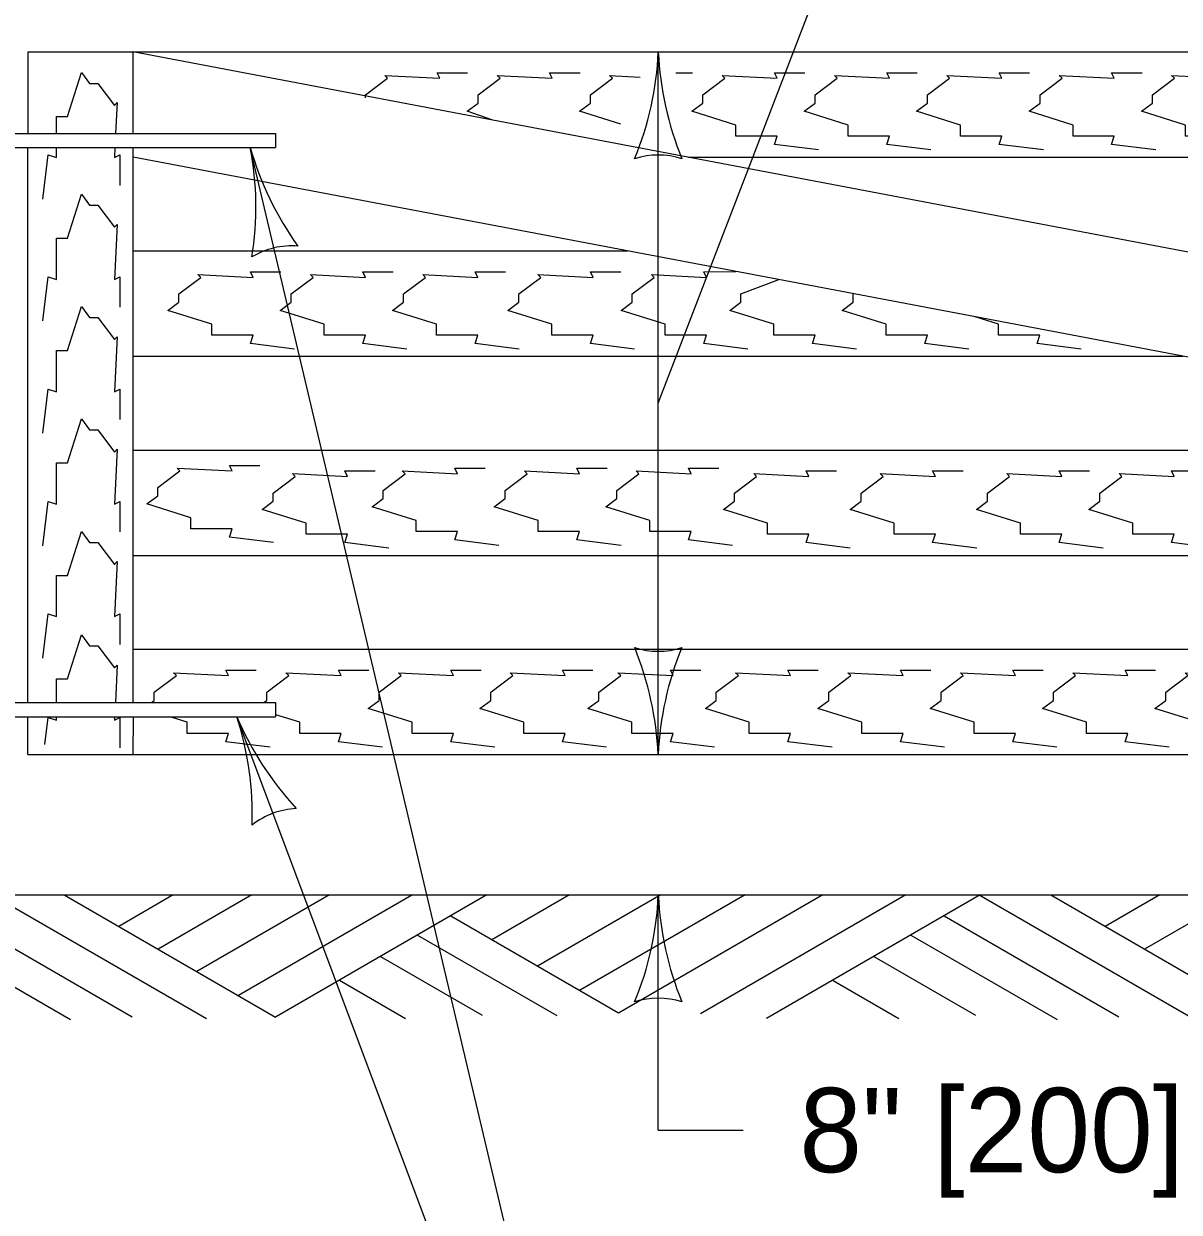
# Model space of a CAD drawing. Extents: x 49991.4 to 50021, y 49987.6 to 50011.4.
# Drawn here: x 50003.336 to 50004.158, y 50009.357 to 50010.203 of the extents above; entities that cross this region are included whole.
import ezdxf

# ---------------------------------------------------------------- set-up
doc = ezdxf.new("R2010")
doc.units = 0
for name, color, linetype in [('Level 1', 7, 'Continuous'), ('Level 2', 7, 'Continuous'), ('Level 3', 7, 'Continuous')]:
    doc.layers.add(name, color=color, linetype=linetype)

msp = doc.modelspace()

# ---------------------------------------------------------------- linework, layer by layer
at = {"layer": 'Level 1'}
for p, q in [((50003.3389, 50010.1834), (50005.6927, 50010.1834)), ((50003.3389, 50010.1834), (50003.3389, 50010.1253)), ((50005.6552, 50009.7582), (50003.4138, 50010.1834)), ((50003.4138, 50010.1834), (50003.4138, 50010.1253)), ((50003.3152, 50010.1253), (50003.5152, 50010.1253)), ((50003.5152, 50010.1253), (50003.5152, 50010.1153)), ((50003.2927, 50010.1153), (50003.5152, 50010.1153)), ((50003.3389, 50009.7202), (50003.3389, 50010.1153)), ((50003.4139, 50009.7202), (50003.4139, 50010.1153)), ((50005.6552, 50009.6833), (50003.4139, 50010.1085)), ((50003.80916, 50010.1084), (50005.6552, 50010.1084)), ((50003.4139, 50010.0417), (50003.76601, 50010.0417)), ((50003.4139, 50009.9667), (50004.16135, 50009.9667)), ((50003.4139, 50009.9), (50004.51294, 50009.9)), ((50003.4139, 50009.825), (50004.90828, 50009.825)), ((50003.4139, 50009.7582), (50005.26039, 50009.7582)), ((50003.3152, 50009.7202), (50003.5152, 50009.7202)), ((50003.5152, 50009.7202), (50003.5152, 50009.7102)), ((50003.2927, 50009.7102), (50003.5152, 50009.7102)), ((50003.3389, 50009.6833), (50003.3389, 50009.7102)), ((50003.41388, 50009.7102), (50003.41381, 50009.6833)), ((50003.3389, 50009.6833), (50005.7302, 50009.6833)), ((50001.4073, 50009.5833), (50004.5539, 50009.5833)), ((50003.3139, 50009.5833), (50003.4661, 50009.4954)), ((50003.3649, 50009.5833), (50003.51535, 50009.49641)), ((50003.44245, 50009.5833), (50003.40365, 50009.56092)), ((50003.49846, 50009.5833), (50003.43164, 50009.54475)), ((50003.55374, 50009.5833), (50003.45929, 50009.52879)), ((50003.6128, 50009.5833), (50003.4889, 50009.5117)), ((50003.6658, 50009.5833), (50003.51535, 50009.49641)), ((50003.7245, 50009.5833), (50003.66935, 50009.55147)), ((50003.7896, 50009.5833), (50003.70186, 50009.53263)), ((50003.84956, 50009.5833), (50003.7317, 50009.5153)), ((50003.90484, 50009.5833), (50003.7593, 50009.4993)), ((50003.9639, 50009.5833), (50003.8177, 50009.4988)), ((50004.0169, 50009.5833), (50003.8647, 50009.4954)), ((50004.0161, 50009.5833), (50004.1683, 50009.4954)), ((50004.0671, 50009.5833), (50004.21755, 50009.49641)), ((50004.14465, 50009.5833), (50004.10585, 50009.56092)), ((50004.20066, 50009.5833), (50004.13384, 50009.54475)), ((50003.28896, 50009.56843), (50003.4133, 50009.4966)), ((50003.64006, 50009.56843), (50003.75935, 50009.49933)), ((50003.99116, 50009.56843), (50004.1155, 50009.4966)), ((50003.2653, 50009.55477), (50003.3693, 50009.4947)), ((50003.6164, 50009.55477), (50003.7155, 50009.4976)), ((50003.9675, 50009.55477), (50004.0715, 50009.4947)), ((50003.59006, 50009.53956), (50003.6623, 50009.4978)), ((50003.94116, 50009.53956), (50004.0134, 50009.4978)), ((50003.56081, 50009.52267), (50003.6079, 50009.4954)), ((50003.9122, 50009.5225), (50003.959, 50009.4954))]:
    msp.add_line(p, q, dxfattribs=at)
for points in [[(50003.3594, 50010.1253), (50003.3594, 50010.1375), (50003.3673, 50010.1375), (50003.3771, 50010.1688), (50003.3829, 50010.161), (50003.3888, 50010.161), (50003.4006, 50010.1453), (50003.4026, 50010.1473), (50003.40143, 50010.1253)], [(50003.5794, 50010.1508), (50003.5794, 50010.1528), (50003.5951, 50010.1646), (50003.5931, 50010.1666), (50003.6323, 50010.1646), (50003.6304, 50010.1685), (50003.652, 50010.1685)], [(50003.66915, 50010.13496), (50003.6516, 50010.1411), (50003.6594, 50010.1469), (50003.6594, 50010.1528), (50003.6751, 50010.1646), (50003.6731, 50010.1666), (50003.7123, 50010.1646), (50003.7104, 50010.1685), (50003.732, 50010.1685)], [(50003.7611, 50010.1319), (50003.7316, 50010.1411), (50003.7394, 50010.1469), (50003.7394, 50010.1528), (50003.7551, 50010.1646), (50003.7531, 50010.1666), (50003.7747, 50010.1655)], [(50003.8002, 50010.1685), (50003.812, 50010.1685)], [(50003.9018, 50010.1136), (50003.8704, 50010.1175), (50003.8723, 50010.1234), (50003.8429, 50010.1234), (50003.8429, 50010.1313), (50003.8116, 50010.1411), (50003.8194, 50010.1469), (50003.8194, 50010.1528), (50003.8351, 50010.1646), (50003.8331, 50010.1666), (50003.8723, 50010.1646), (50003.8704, 50010.1685), (50003.892, 50010.1685)], [(50003.9818, 50010.1136), (50003.9504, 50010.1175), (50003.9523, 50010.1234), (50003.9229, 50010.1234), (50003.9229, 50010.1313), (50003.8916, 50010.1411), (50003.8994, 50010.1469), (50003.8994, 50010.1528), (50003.9151, 50010.1646), (50003.9131, 50010.1666), (50003.9523, 50010.1646), (50003.9504, 50010.1685), (50003.972, 50010.1685)], [(50004.0618, 50010.1136), (50004.0304, 50010.1175), (50004.0323, 50010.1234), (50004.0029, 50010.1234), (50004.0029, 50010.1313), (50003.9716, 50010.1411), (50003.9794, 50010.1469), (50003.9794, 50010.1528), (50003.9951, 50010.1646), (50003.9931, 50010.1666), (50004.0323, 50010.1646), (50004.0304, 50010.1685), (50004.052, 50010.1685)], [(50004.1418, 50010.1136), (50004.1104, 50010.1175), (50004.1123, 50010.1234), (50004.0829, 50010.1234), (50004.0829, 50010.1313), (50004.0516, 50010.1411), (50004.0594, 50010.1469), (50004.0594, 50010.1528), (50004.0751, 50010.1646), (50004.0731, 50010.1666), (50004.1123, 50010.1646), (50004.1104, 50010.1685), (50004.132, 50010.1685)], [(50004.2218, 50010.1136), (50004.1904, 50010.1175), (50004.1923, 50010.1234), (50004.1629, 50010.1234), (50004.1629, 50010.1313), (50004.1316, 50010.1411), (50004.1394, 50010.1469), (50004.1394, 50010.1528), (50004.1551, 50010.1646), (50004.1531, 50010.1666), (50004.1923, 50010.1646), (50004.1904, 50010.1685), (50004.212, 50010.1685)], [(50003.3496, 50010.0786), (50003.3535, 50010.11), (50003.3594, 50010.1081), (50003.3594, 50010.1153)], [(50003.40094, 50010.1153), (50003.4006, 50010.1081), (50003.4045, 50010.11), (50003.4045, 50010.0884)], [(50003.3496, 50009.9919), (50003.3535, 50010.0233), (50003.3594, 50010.0214), (50003.3594, 50010.0508), (50003.3673, 50010.0508), (50003.3771, 50010.0821), (50003.3829, 50010.0743), (50003.3888, 50010.0743), (50003.4006, 50010.0586), (50003.4026, 50010.0606), (50003.4006, 50010.0214), (50003.4045, 50010.0233), (50003.4045, 50010.0017)], [(50003.5288, 50009.9719), (50003.4974, 50009.9758), (50003.4993, 50009.9817), (50003.4699, 50009.9817), (50003.4699, 50009.9896), (50003.4386, 50009.9994), (50003.4464, 50010.0052), (50003.4464, 50010.0111), (50003.4621, 50010.0229), (50003.4601, 50010.0249), (50003.4993, 50010.0229), (50003.4974, 50010.0268), (50003.519, 50010.0268)], [(50003.6088, 50009.9719), (50003.5774, 50009.9758), (50003.5793, 50009.9817), (50003.5499, 50009.9817), (50003.5499, 50009.9896), (50003.5186, 50009.9994), (50003.5264, 50010.0052), (50003.5264, 50010.0111), (50003.5421, 50010.0229), (50003.5401, 50010.0249), (50003.5793, 50010.0229), (50003.5774, 50010.0268), (50003.599, 50010.0268)], [(50003.6888, 50009.9719), (50003.6574, 50009.9758), (50003.6593, 50009.9817), (50003.6299, 50009.9817), (50003.6299, 50009.9896), (50003.5986, 50009.9994), (50003.6064, 50010.0052), (50003.6064, 50010.0111), (50003.6221, 50010.0229), (50003.6201, 50010.0249), (50003.6593, 50010.0229), (50003.6574, 50010.0268), (50003.679, 50010.0268)], [(50003.7708, 50009.9719), (50003.7394, 50009.9758), (50003.7413, 50009.9817), (50003.7119, 50009.9817), (50003.7119, 50009.9896), (50003.6806, 50009.9994), (50003.6884, 50010.0052), (50003.6884, 50010.0111), (50003.7041, 50010.0229), (50003.7021, 50010.0249), (50003.7413, 50010.0229), (50003.7394, 50010.0268), (50003.761, 50010.0268)], [(50003.8515, 50009.9719), (50003.8201, 50009.9758), (50003.822, 50009.9817), (50003.7926, 50009.9817), (50003.7926, 50009.9896), (50003.7613, 50009.9994), (50003.7691, 50010.0052), (50003.7691, 50010.0111), (50003.7848, 50010.0229), (50003.7828, 50010.0249), (50003.822, 50010.0229), (50003.8201, 50010.0268), (50003.84299, 50010.0271)], [(50003.9288, 50009.9719), (50003.8974, 50009.9758), (50003.8993, 50009.9817), (50003.8699, 50009.9817), (50003.8699, 50009.9896), (50003.8386, 50009.9994), (50003.8464, 50010.0052), (50003.8464, 50010.0111), (50003.87343, 50010.02132)], [(50004.0088, 50009.9719), (50003.9774, 50009.9758), (50003.9793, 50009.9817), (50003.9499, 50009.9817), (50003.9499, 50009.9896), (50003.9186, 50009.9994), (50003.9264, 50010.0052), (50003.9264, 50010.01127)], [(50003.3496, 50009.9119), (50003.3535, 50009.9433), (50003.3594, 50009.9414), (50003.3594, 50009.9708), (50003.3673, 50009.9708), (50003.3771, 50010.0021), (50003.3829, 50009.9943), (50003.3888, 50009.9943), (50003.4006, 50009.9786), (50003.4026, 50009.9806), (50003.4006, 50009.9414), (50003.4045, 50009.9433), (50003.4045, 50009.9217)], [(50004.0888, 50009.9719), (50004.0574, 50009.9758), (50004.0593, 50009.9817), (50004.0299, 50009.9817), (50004.0299, 50009.9896), (50004.01333, 50009.99478)], [(50003.3496, 50009.8319), (50003.3535, 50009.8633), (50003.3594, 50009.8614), (50003.3594, 50009.8908), (50003.3673, 50009.8908), (50003.3771, 50009.9221), (50003.3829, 50009.9143), (50003.3888, 50009.9143), (50003.4006, 50009.8986), (50003.4026, 50009.9006), (50003.4006, 50009.8614), (50003.4045, 50009.8633), (50003.4045, 50009.8417)], [(50003.5139, 50009.8341), (50003.4825, 50009.838), (50003.4844, 50009.8439), (50003.455, 50009.8439), (50003.455, 50009.8518), (50003.4237, 50009.8616), (50003.4315, 50009.8674), (50003.4315, 50009.8733), (50003.4472, 50009.8851), (50003.4452, 50009.8871), (50003.4844, 50009.8851), (50003.4825, 50009.889), (50003.5041, 50009.889)], [(50003.596, 50009.8302), (50003.5646, 50009.8341), (50003.5665, 50009.84), (50003.5371, 50009.84), (50003.5371, 50009.8479), (50003.5058, 50009.8577), (50003.5136, 50009.8635), (50003.5136, 50009.8694), (50003.5293, 50009.8812), (50003.5273, 50009.8832), (50003.5665, 50009.8812), (50003.5646, 50009.8851), (50003.5862, 50009.8851)], [(50003.6742, 50009.8321), (50003.6428, 50009.836), (50003.6447, 50009.8419), (50003.6153, 50009.8419), (50003.6153, 50009.8498), (50003.584, 50009.8596), (50003.5918, 50009.8654), (50003.5918, 50009.8713), (50003.6075, 50009.8831), (50003.6055, 50009.8851), (50003.6447, 50009.8831), (50003.6428, 50009.887), (50003.6644, 50009.887)], [(50003.7612, 50009.8321), (50003.7298, 50009.836), (50003.7317, 50009.8419), (50003.7023, 50009.8419), (50003.7023, 50009.8498), (50003.671, 50009.8596), (50003.6788, 50009.8654), (50003.6788, 50009.8713), (50003.6945, 50009.8831), (50003.6925, 50009.8851), (50003.7317, 50009.8831), (50003.7298, 50009.887), (50003.7514, 50009.887)], [(50003.8406, 50009.8321), (50003.8092, 50009.836), (50003.8111, 50009.8419), (50003.7817, 50009.8419), (50003.7817, 50009.8498), (50003.7504, 50009.8596), (50003.7582, 50009.8654), (50003.7582, 50009.8713), (50003.7739, 50009.8831), (50003.7719, 50009.8851), (50003.8111, 50009.8831), (50003.8092, 50009.887), (50003.8308, 50009.887)], [(50003.9244, 50009.8302), (50003.893, 50009.8341), (50003.8949, 50009.84), (50003.8655, 50009.84), (50003.8655, 50009.8479), (50003.8342, 50009.8577), (50003.842, 50009.8635), (50003.842, 50009.8694), (50003.8577, 50009.8812), (50003.8557, 50009.8832), (50003.8949, 50009.8812), (50003.893, 50009.8851), (50003.9146, 50009.8851)], [(50004.0144, 50009.8302), (50003.983, 50009.8341), (50003.9849, 50009.84), (50003.9555, 50009.84), (50003.9555, 50009.8479), (50003.9242, 50009.8577), (50003.932, 50009.8635), (50003.932, 50009.8694), (50003.9477, 50009.8812), (50003.9457, 50009.8832), (50003.9849, 50009.8812), (50003.983, 50009.8851), (50004.0046, 50009.8851)], [(50004.1044, 50009.8302), (50004.073, 50009.8341), (50004.0749, 50009.84), (50004.0455, 50009.84), (50004.0455, 50009.8479), (50004.0142, 50009.8577), (50004.022, 50009.8635), (50004.022, 50009.8694), (50004.0377, 50009.8812), (50004.0357, 50009.8832), (50004.0749, 50009.8812), (50004.073, 50009.8851), (50004.0946, 50009.8851)], [(50004.1844, 50009.8302), (50004.153, 50009.8341), (50004.1549, 50009.84), (50004.1255, 50009.84), (50004.1255, 50009.8479), (50004.0942, 50009.8577), (50004.102, 50009.8635), (50004.102, 50009.8694), (50004.1177, 50009.8812), (50004.1157, 50009.8832), (50004.1549, 50009.8812), (50004.153, 50009.8851), (50004.1746, 50009.8851)], [(50003.3496, 50009.7519), (50003.3535, 50009.7833), (50003.3594, 50009.7814), (50003.3594, 50009.8108), (50003.3673, 50009.8108), (50003.3771, 50009.8421), (50003.3829, 50009.8343), (50003.3888, 50009.8343), (50003.4006, 50009.8186), (50003.4026, 50009.8206), (50003.4006, 50009.7814), (50003.4045, 50009.7833), (50003.4045, 50009.7617)], [(50003.3594, 50009.7202), (50003.3594, 50009.7371), (50003.3673, 50009.7371), (50003.3771, 50009.7684), (50003.3829, 50009.7606), (50003.3888, 50009.7606), (50003.4006, 50009.7449), (50003.4026, 50009.7469), (50003.40129, 50009.7202)], [(50003.427, 50009.7203), (50003.429, 50009.7218), (50003.429, 50009.7277), (50003.4447, 50009.7395), (50003.4427, 50009.7415), (50003.4819, 50009.7395), (50003.48, 50009.7434), (50003.5016, 50009.7434)], [(50003.5072, 50009.7205), (50003.509, 50009.7218), (50003.509, 50009.7277), (50003.5247, 50009.7395), (50003.5227, 50009.7415), (50003.5619, 50009.7395), (50003.56, 50009.7434), (50003.5816, 50009.7434)], [(50003.6714, 50009.6885), (50003.64, 50009.6924), (50003.6419, 50009.6983), (50003.6125, 50009.6983), (50003.6125, 50009.7062), (50003.5812, 50009.716), (50003.589, 50009.7218), (50003.589, 50009.7277), (50003.6047, 50009.7395), (50003.6027, 50009.7415), (50003.6419, 50009.7395), (50003.64, 50009.7434), (50003.6616, 50009.7434)], [(50003.7509, 50009.6885), (50003.7195, 50009.6924), (50003.7214, 50009.6983), (50003.692, 50009.6983), (50003.692, 50009.7062), (50003.6607, 50009.716), (50003.6685, 50009.7218), (50003.6685, 50009.7277), (50003.6842, 50009.7395), (50003.6822, 50009.7415), (50003.7214, 50009.7395), (50003.7195, 50009.7434), (50003.7411, 50009.7434)], [(50003.8277, 50009.6885), (50003.7963, 50009.6924), (50003.7982, 50009.6983), (50003.7688, 50009.6983), (50003.7688, 50009.7062), (50003.7375, 50009.716), (50003.7453, 50009.7218), (50003.7453, 50009.7277), (50003.761, 50009.7395), (50003.759, 50009.7415), (50003.7982, 50009.7395), (50003.7963, 50009.7434), (50003.8179, 50009.7434)], [(50003.9114, 50009.6885), (50003.88, 50009.6924), (50003.8819, 50009.6983), (50003.8525, 50009.6983), (50003.8525, 50009.7062), (50003.8212, 50009.716), (50003.829, 50009.7218), (50003.829, 50009.7277), (50003.8447, 50009.7395), (50003.8427, 50009.7415), (50003.8819, 50009.7395), (50003.88, 50009.7434), (50003.9016, 50009.7434)], [(50003.9914, 50009.6885), (50003.96, 50009.6924), (50003.9619, 50009.6983), (50003.9325, 50009.6983), (50003.9325, 50009.7062), (50003.9012, 50009.716), (50003.909, 50009.7218), (50003.909, 50009.7277), (50003.9247, 50009.7395), (50003.9227, 50009.7415), (50003.9619, 50009.7395), (50003.96, 50009.7434), (50003.9816, 50009.7434)], [(50004.0714, 50009.6885), (50004.04, 50009.6924), (50004.0419, 50009.6983), (50004.0125, 50009.6983), (50004.0125, 50009.7062), (50003.9812, 50009.716), (50003.989, 50009.7218), (50003.989, 50009.7277), (50004.0047, 50009.7395), (50004.0027, 50009.7415), (50004.0419, 50009.7395), (50004.04, 50009.7434), (50004.0616, 50009.7434)], [(50004.1514, 50009.6885), (50004.12, 50009.6924), (50004.1219, 50009.6983), (50004.0925, 50009.6983), (50004.0925, 50009.7062), (50004.0612, 50009.716), (50004.069, 50009.7218), (50004.069, 50009.7277), (50004.0847, 50009.7395), (50004.0827, 50009.7415), (50004.1219, 50009.7395), (50004.12, 50009.7434), (50004.1416, 50009.7434)], [(50004.2314, 50009.6885), (50004.2, 50009.6924), (50004.2019, 50009.6983), (50004.1725, 50009.6983), (50004.1725, 50009.7062), (50004.1412, 50009.716), (50004.149, 50009.7218), (50004.149, 50009.7277), (50004.1647, 50009.7395), (50004.1627, 50009.7415), (50004.2019, 50009.7395), (50004.2, 50009.7434), (50004.2216, 50009.7434)], [(50003.3511, 50009.6904), (50003.3535, 50009.7096), (50003.3594, 50009.7077), (50003.3594, 50009.7102)], [(50003.40072, 50009.7102), (50003.4006, 50009.7077), (50003.4045, 50009.7096), (50003.4045, 50009.688)], [(50003.5114, 50009.6885), (50003.48, 50009.6924), (50003.4819, 50009.6983), (50003.4525, 50009.6983), (50003.4525, 50009.7062), (50003.4418, 50009.7096)], [(50003.5914, 50009.6885), (50003.56, 50009.6924), (50003.5619, 50009.6983), (50003.5325, 50009.6983), (50003.5325, 50009.7062), (50003.5154, 50009.7115)]]:
    msp.add_lwpolyline(points, dxfattribs=at)
at = {"layer": 'Level 3'}
for p, q in [((50003.7877, 50009.6833), (50003.7877, 50010.1834)), ((50003.77324, 50008.9483), (50003.4973, 50010.1153)), ((50003.77324, 50008.9483), (50003.48766, 50009.7102)), ((50003.7877, 50009.416), (50003.7877, 50009.5833)), ((50003.7877, 50009.416), (50003.8481, 50009.416))]:
    msp.add_line(p, q, dxfattribs=at)
msp.add_lwpolyline([(50003.7877, 50009.93335), (50003.92403, 50010.2878), (50003.9885, 50010.2878)], dxfattribs=at)
for centre, radius, start, end in [((50003.56557, 50010.19256), 0.22232, 337.45601, 357.63952), ((50004.02041, 50010.19489), 0.233, 182.82731, 202.07716), ((50003.27902, 50010.0731), 0.22232, 350.75923, 10.94274), ((50003.72112, 50010.18003), 0.233, 196.13053, 215.38038), ((50003.7877, 50010.05519), 0.05477, 72.13882, 107.86118), ((50003.5268, 50009.99053), 0.05477, 85.44204, 121.1644), ((50003.7877, 50009.81151), 0.05477, 252.13882, 287.86118), ((50003.55499, 50009.67181), 0.233, 2.82731, 22.07716), ((50004.00983, 50009.67414), 0.22232, 157.45601, 177.63952), ((50003.27644, 50009.64081), 0.22232, 358.0033, 18.18681), ((50003.70153, 50009.80264), 0.233, 203.3746, 222.62445), ((50003.53266, 50009.59014), 0.05477, 92.68611, 128.40847), ((50003.56557, 50009.59246), 0.22232, 337.45601, 357.63952), ((50004.02041, 50009.59479), 0.233, 182.82731, 202.07716), ((50003.7877, 50009.45509), 0.05477, 72.13882, 107.86118)]:
    msp.add_arc(centre, radius, start, end, dxfattribs=at)

# ---------------------------------------------------------------- texts
at = {"layer": 'Level 2'}
msp.add_text('8" [200]', height=0.06, dxfattribs=at).set_placement((50003.8881, 50009.386))

doc.saveas('drawing.dxf')
